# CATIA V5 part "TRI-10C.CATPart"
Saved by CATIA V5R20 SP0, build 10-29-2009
Part number: _TRI-10C
Definition: NONE
Nomenclature: _TRI-10C
Source: Unknown
Description: PART-_TRI-10C-DESC
Bounding box of the stored display mesh (mm): x 0 to 13.5, y -5 to 5, z -5 to 5
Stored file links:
  C:\Users\Utente\Desktop\IO LAVORO\3D X SITO CF\X SITO\PLASTICA\TRI\TRI-10C.CATPart
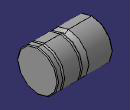
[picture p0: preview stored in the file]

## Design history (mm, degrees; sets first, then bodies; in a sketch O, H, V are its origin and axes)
Body1 "_TRI-10C" (main body)
  Solid1: solid without history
